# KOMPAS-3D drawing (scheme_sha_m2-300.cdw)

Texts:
  Шкаф автоматики Схема электрическая соединений
  Никулов
  Текст на чертеже
  Размерные надписи
  Шероховатость
  Линия-выноска #1
  Линия-выноска #2
  Линия-выноска #3
  Отклонения формы и база
  Заголовок таблицы
  Ячейка таблицы
  Стрелка вида
  Обозначение изменения
  Фигурная скобка
  Номер узла
  Марка координационной оси
  VRCB
  Выносная надпись
  Обозначение узла
  Марка/позиционное обозначение с линией-выноской
  Марка/позиционное обозначение на линии
  Марка/позиционное обозначение без линии-выноски
  Примечание: На маркировке двухуровневых клемм клеммников ХТ1,
  ХТ2 и ХТ3   нечётному номеру контакта соответствует
  нижний,   чётному - верхний контакт.
  Адрес
  Цепь
  Конт.
  ХТ2.1 слаботочный (1 зона) / - 34
  ДПД ГВС1 1 зоны
  ДПД ГВС2 1 зоны
  ДПД ГВС3 1 зоны
  Расширитель-
  ный  бак
  общий
  макс. уровень
  мин. уровень
  ДПД ХВС1 1 зоны
  ДПД ХВС2 1 зоны
  ДПД ХВС3 1 зоны
  Дренаж
  ЭКМ ЦНО
  ЭКМ ХВС
  ДПД ХВС4 1 зоны
  ДПД ДРН
  ЭКМ ГВС
  Разъём
  МАСТЕР Т-300v2
  РП14А-30 Ш6
  ТпрТС
  ХТ2.2  слаботочный (1 зона) / - 34
  Tahoma
  ТобрТС
  ТпрОТ-1з
  ТобрОТ-1з
  Тнв
  ТпрГВС-1з
  Рпр1
  Робр1
  Рпр1вх
  Gтс
  Контроль воды
  ДПД ЦНО3 1 зоны
  ДПД ЦНО2 1 зоны
  ДПД ЦНО1 1 зоны
  ДПД ПНО1
  ДПД ПНО2
  ХТ3/31
  +Uд
  ХТ3/19
  ХТ3 слаботочный (2 зона) / - 16
  ДПД ГВС1 2 зоны
  ДПД ГВС2 2 зоны
  ДПД ГВС3 2 зоны
  ДПД ХВС-0 2 зоны
  Контроль двери
  Рпр2вх
  Рпр2
  ТпрОТ-2з
  ТобрОТ-2з
  ТпрГВС-2з
  Робр2
  ДПД ЦНО-0 2 зоны
  Разъем
  ХВ5
  ХВ6
  ХВ7
  ХВ10
  ХВ8
  ХВ9
  ХВ11
  ХВ13
  ХВ12
  "Рег. ГВС
  SF4
  SF7
  SF8
  SF9
  SF2
  "Кл.
  ПО"
  "Рег. ОТ
  "Рег. ПД
  "Розетка"
  Дверца шкафа автоматики
  "МАСТЕР
  Земля
  SF11
  "Осве-
  щение"
  HLG
  Symbol
  HLR
  "Обобщенный
  сигнал  аварии"
  SF12
  "Резерв"
  "Кл.ПО"
  ХТ1/27
  ХТ1/31
  ХТ1/35
  ХТ1/39
  SF1
  "Общий"
  Розетка
  ХВ1
  Фаза
  (от АВР)
  ХТ1.1 силовой / - 39
  Ноль
  Автомат
  Резерв
  ХВ2.1
  ХТ1/68
  ХТ1/61
  ХТ1/65
  ХТ1/57
  SF6
  SF5
  SF3
  РП14А-30 Г6
  SA1/ I /4
  SA2/ I /4
  SA3/ I /4
  SA4/ I /4
  ХТ1/60
  HLR/F1
  SF2/2
  SA4/ II /4
  SA3/ II /4
  SA2/ II /4
  SA1/ II /4
  ХТ1.2 силовой / - 39
  Управление насосом
  № 1 ХВС 1-й зоны
  Фаза авт.
  МП авт.
  № 2 ХВС 1-й зоны
  № 3 ХВС 1-й зоны
  № 4 ХВС 1-й зоны
  № 1 ГВС 1-й зоны
  № 2 ГВС 1-й зоны
  № 3 ГВС 1-й зоны
  № 1 ЦНО 1-й зоны
  № 2 ЦНО 1-й зоны
  № 3 ЦНО 1-й зоны
  № 1 ПНО
  № 2 ПНО
  ДРН
  Управление клапаном
  подпитки отопления
  (Кл. ПО)
  Фаза ручн.
  Откр ПО
  Закр ПО
  регулятора ГВС 1-й зоны
  (Рег. ГВС
  Закр РГВС-1з
  Откр РГВС-1з
  регулятора отопления
  (Рег. ОТ
  Закр РОТ-1з
  Откр РОТ-1з
  регулятора перепада
  давления 1-й зоны
  (Рег. ПД
  Закр РПД
  Откр РПД
  ХВ3
  ХТ1/75
  SA7/ I /4
  SA7/ II /4
  SA5/ I /4
  SA5/ II /4
  SA6/ I /4
  SA6/ II /4
  ХТ1.3 силовой / - 39
  № 1 ХВС 2-й зоны
  № 2 ХВС 2-й зоны
  № 1 ГВС 2-й зоны
  № 2 ГВС 2-й зоны
  № 3 ГВС 2-й зоны
  № 1 ЦНО 2-й зоны
  № 2 ЦНО 2-й зоны
  давления 2-й зоны
  регулятора ГВС 2-й зоны
  Закр РД
  Откр РД
  Закр РГВС-2з
  Откр РГВС-2з
  Закр РОТ-2з
  Откр РОТ-2з
  ХВ4
  ХТ1/71
  ХТ1/42
  ХВ2.2
  SA2
  SA3
  SA4
  SA5
  SA6
  SA7
  SA1
  QF10
  Коммутация цепей переключателя SA
  вид со стороны монтажа
  "Авт."
  "0ткл."
  "Ручн."
  CONTINUOUS0
  Шкаф автоматики
  Схема электрическая
  соединений
  Шкаф автоматики ШАМ2-300-
  ООО
  "ЭТК-Прибор"
  типа ША М2-300
  Шкаф автоматики ШАМ2-300
  ШАМ2-300
Dimensions and other numbers on the sheet: 7; 1; 2; 3; 4; 5; 6; 8; 9; 10; 11; 12; 13; 14; 15; 16; 1 зоны; 17; 18; 19; 20; 21; 22; 23; 24; 25; 26; 27; 28; 29; 30; 31; 32; 35; 33; 34; 36; 37; 38; 39; 40; 41; 42; 43; 44; 45; 46; 47; 48; 49; 50; 51; 52; 53; 54; 55; 56; 57; 58; 59; 60; 61; 62; 63; 64; 65; 66; 67; 68; +24В; 2 зоны; 2 зона"; 1 зона"; 16А; 78; 77; 76; 75; 74; 73; 72; 71; 70; 69; 1 зона); 1-й зоны; 2 зона); 2-й зоны; 0,3; 0,2; 0,4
